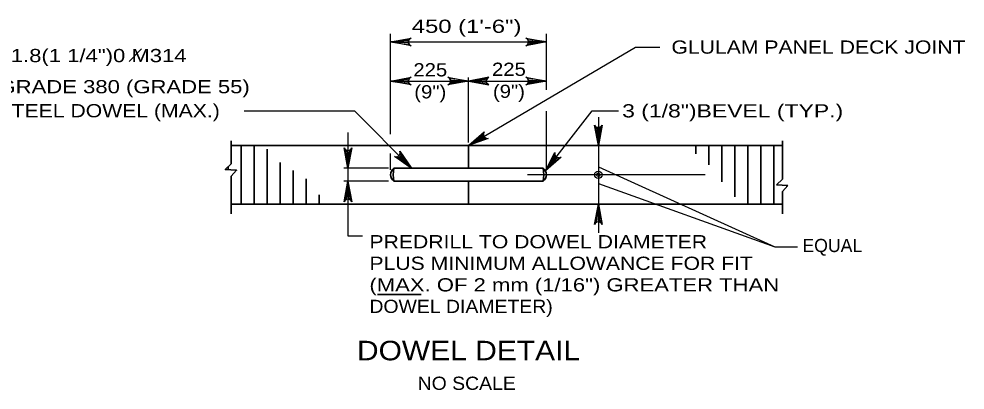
# Model space of a CAD drawing. Extents: x -11 to 79, y -154 to 0.
# Drawn here: x 39.49 to 48.09, y -145.73 to -142.36 of the extents above; entities that cross this region are included whole.
import ezdxf
from ezdxf.enums import TextEntityAlignment as Align

# ---------------------------------------------------------------- set-up
doc = ezdxf.new("R2010")
doc.units = 0
doc.header["$LTSCALE"] = 0.048
for name, color, linetype, lineweight in [('2', 7, 'Continuous', 35), ('3', 7, 'Continuous', 25), ('5', 7, 'Continuous', 25)]:
    doc.layers.add(name, color=color, linetype=linetype, lineweight=lineweight)

msp = doc.modelspace()

# ---------------------------------------------------------------- hatches: boundary and pattern name
at = {"layer": '2'}
msp.add_hatch(color=256, dxfattribs=at).paths.add_polyline_path([(44.27675, -143.73675), (44.28058, -143.73375), (44.27875, -143.73233)])
at = {"layer": '3'}
for points in [[(43.57692, -143.50542), (43.58158, -143.50408), (43.58042, -143.502)], [(42.99258, -143.61842), (42.96583, -143.64508), (43.05925, -143.71208)]]:
    msp.add_hatch(color=256, dxfattribs=at).paths.add_polyline_path(points)

# ---------------------------------------------------------------- linework, layer by layer
at = {"layer": '2'}
for p, q in [((41.41967, -143.4615), (41.41967, -143.67217)), ((41.41967, -143.50542), (46.43392, -143.50542)), ((43.57692, -143.71208), (43.57692, -143.50542)), ((46.43392, -143.4615), (46.43392, -143.80992)), ((41.41967, -143.78458), (41.41967, -144.12508)), ((43.57692, -144.03692), (43.57692, -143.83025)), ((46.43392, -143.80992), (46.37875, -143.862)), ((46.37875, -143.862), (46.48275, -143.86775)), ((41.41967, -144.03692), (46.43392, -144.03692))]:
    msp.add_line(p, q, dxfattribs=at)
at = {"layer": '2', "lineweight": 25}
msp.add_lwpolyline([(44.27675, -143.73675), (44.70158, -143.19142), (44.94242, -143.19142)], dxfattribs=at)
at = {"layer": '2'}
for points in [[(41.41967, -143.67217), (41.3645, -143.72425), (41.4685, -143.73), (41.41967, -143.78458)], [(46.48275, -143.86775), (46.43392, -143.92233), (46.43392, -144.12508)]]:
    msp.add_lwpolyline(points, dxfattribs=at)
at = {"layer": '2', "lineweight": 25}
msp.add_lwpolyline([(44.27675, -143.73675), (44.28058, -143.73375), (44.27875, -143.73233)], close=True, dxfattribs=at)
at = {"layer": '3'}
for p, q in [((42.86825, -143.403), (42.86825, -142.48975)), ((44.28558, -143), (44.28558, -142.48975)), ((42.86825, -142.56433), (44.28558, -142.56433)), ((42.86825, -142.91983), (44.28558, -142.91983)), ((43.57692, -143.4765), (43.57692, -142.8875)), ((41.53575, -143.19042), (42.54, -143.19042)), ((43.05917, -143.71208), (42.54, -143.19042)), ((44.28558, -143.725), (44.28558, -143.19183)), ((44.75808, -143.2465), (44.75808, -144.29992)), ((42.48108, -143.38842), (42.48108, -144.32467)), ((42.86825, -143.725), (42.86825, -143.57733)), ((44.75808, -143.7), (46.36408, -144.42525)), ((42.8485, -143.71208), (42.44408, -143.71208)), ((45.73042, -143.77092), (44.11267, -143.77092)), ((42.8485, -143.83025), (42.44208, -143.83025)), ((42.48108, -144.32467), (42.61242, -144.32467))]:
    msp.add_line(p, q, dxfattribs=at)
at = {"layer": '3', "lineweight": 35}
for p, q in [((40.48967, -142.74083), (40.60225, -142.62817)), ((42.75067, -144.85942), (43.14592, -144.85942))]:
    msp.add_line(p, q, dxfattribs=at)
at = {"layer": '3'}
for points in [[(42.86825, -142.56433), (43.05467, -142.52942), (43.04033, -142.53933), (43.03292, -142.55183), (43.03075, -142.56433), (43.03292, -142.57683), (43.04033, -142.58933), (43.05467, -142.59925), (42.86825, -142.56433), (43.04033, -142.58933), (43.03292, -142.57683), (42.86825, -142.56433), (43.03075, -142.56433), (43.03292, -142.55183), (42.86825, -142.56433), (43.04033, -142.53933)], [(44.28558, -142.56433), (44.09917, -142.59925), (44.1135, -142.58933), (44.12092, -142.57683), (44.12308, -142.56433), (44.12092, -142.55183), (44.1135, -142.53933), (44.09917, -142.52942), (44.28558, -142.56433), (44.1135, -142.53933), (44.12092, -142.55183), (44.28558, -142.56433), (44.12308, -142.56433), (44.12092, -142.57683), (44.28558, -142.56433), (44.1135, -142.58933)], [(43.57692, -143.50542), (45.09617, -142.61083), (45.31717, -142.61083)], [(42.86825, -142.91983), (43.05467, -142.88492), (43.04033, -142.89483), (43.03292, -142.90733), (43.03075, -142.91983), (43.03292, -142.93233), (43.04033, -142.94483), (43.05467, -142.95475), (42.86825, -142.91983), (43.04033, -142.94483), (43.03292, -142.93233), (42.86825, -142.91983), (43.03075, -142.91983), (43.03292, -142.90733), (42.86825, -142.91983), (43.04033, -142.89483)], [(43.57692, -142.91983), (43.3905, -142.95475), (43.40483, -142.94483), (43.41225, -142.93233), (43.41442, -142.91983), (43.41225, -142.90733), (43.40483, -142.89483), (43.3905, -142.88492), (43.57692, -142.91983), (43.40483, -142.89483), (43.41225, -142.90733), (43.57692, -142.91983), (43.41442, -142.91983), (43.41225, -142.93233), (43.57692, -142.91983), (43.40483, -142.94483)], [(43.57692, -142.91983), (43.76333, -142.95475), (43.749, -142.94483), (43.74158, -142.93233), (43.73942, -142.91983), (43.74158, -142.90733), (43.749, -142.89483), (43.76333, -142.88492), (43.57692, -142.91983), (43.749, -142.89483), (43.74158, -142.90733), (43.57692, -142.91983), (43.73942, -142.91983), (43.74158, -142.93233), (43.57692, -142.91983), (43.749, -142.94483)], [(44.28558, -142.91983), (44.09917, -142.95475), (44.1135, -142.94483), (44.12092, -142.93233), (44.12308, -142.91983), (44.12092, -142.90733), (44.1135, -142.89483), (44.09917, -142.88492), (44.28558, -142.91983), (44.1135, -142.89483), (44.12092, -142.90733), (44.28558, -142.91983), (44.12308, -142.91983), (44.12092, -142.93233), (44.28558, -142.91983), (44.1135, -142.94483)], [(44.75808, -143.50542), (44.72317, -143.319), (44.73308, -143.33333), (44.74558, -143.34075), (44.75808, -143.34292), (44.77058, -143.34075), (44.78308, -143.33333), (44.793, -143.319), (44.75808, -143.50542), (44.78308, -143.33333), (44.77058, -143.34075), (44.75808, -143.50542), (44.75808, -143.34292), (44.74558, -143.34075), (44.75808, -143.50542), (44.73308, -143.33333)], [(43.57692, -143.50542), (43.71983, -143.38075), (43.7125, -143.39658), (43.71242, -143.41108), (43.71692, -143.423), (43.72517, -143.43267), (43.73783, -143.43967), (43.75525, -143.44092), (43.57692, -143.50542), (43.73783, -143.43967), (43.72517, -143.43267), (43.57692, -143.50542), (43.71692, -143.423), (43.71242, -143.41108), (43.57692, -143.50542), (43.7125, -143.39658)], [(42.48108, -143.71208), (42.44617, -143.52567), (42.45608, -143.54), (42.46858, -143.54742), (42.48108, -143.54958), (42.49358, -143.54742), (42.50608, -143.54), (42.516, -143.52567), (42.48108, -143.71208), (42.50608, -143.54), (42.49358, -143.54742), (42.48108, -143.71208), (42.48108, -143.54958), (42.46858, -143.54742), (42.48108, -143.71208), (42.45608, -143.54)], [(43.05917, -143.71208), (42.90292, -143.60458), (42.92008, -143.60775), (42.93417, -143.60417), (42.9445, -143.59692), (42.95192, -143.58658), (42.9555, -143.5725), (42.95242, -143.55533), (43.05917, -143.71208), (42.9555, -143.5725), (42.95192, -143.58658), (43.05917, -143.71208), (42.9445, -143.59692), (42.93417, -143.60417), (43.05917, -143.71208), (42.92008, -143.60775)], [(44.27675, -143.73675), (44.36375, -143.56825), (44.36275, -143.58567), (44.36808, -143.59917), (44.37658, -143.60858), (44.38783, -143.61458), (44.40217, -143.61642), (44.41892, -143.61117), (44.27675, -143.73675), (44.40217, -143.61642), (44.38783, -143.61458), (44.27675, -143.73675), (44.37658, -143.60858), (44.36808, -143.59917), (44.27675, -143.73675), (44.36275, -143.58567)], [(42.48108, -143.83025), (42.516, -144.01667), (42.50608, -144.00233), (42.49358, -143.99492), (42.48108, -143.99275), (42.46858, -143.99492), (42.45608, -144.00233), (42.44617, -144.01667), (42.48108, -143.83025), (42.45608, -144.00233), (42.46858, -143.99492), (42.48108, -143.83025), (42.48108, -143.99275), (42.49358, -143.99492), (42.48108, -143.83025), (42.50608, -144.00233)], [(44.75808, -143.85058), (46.36408, -144.42525), (46.56917, -144.42525)], [(44.75808, -144.03692), (44.793, -144.22333), (44.78308, -144.209), (44.77058, -144.20158), (44.75808, -144.19942), (44.74558, -144.20158), (44.73308, -144.209), (44.72317, -144.22333), (44.75808, -144.03692), (44.73308, -144.209), (44.74558, -144.20158), (44.75808, -144.03692), (44.75808, -144.19942), (44.77058, -144.20158), (44.75808, -144.03692), (44.78308, -144.209)]]:
    msp.add_lwpolyline(points, dxfattribs=at)
for points in [[(43.57692, -143.50542), (43.58158, -143.50408), (43.58042, -143.502)], [(42.99258, -143.61842), (42.96583, -143.64508), (43.05925, -143.71208)]]:
    msp.add_lwpolyline(points, close=True, dxfattribs=at)
for radius in [0.03333, 0.01667]:
    msp.add_circle((44.75805, -143.77092), radius, dxfattribs=at)
at = {"layer": '5', "lineweight": 35}
for p, q in [((41.51075, -144.03683), (41.51075, -143.50542)), ((41.62883, -144.03675), (41.62883, -143.50542)), ((45.64458, -143.58042), (45.64458, -143.50542)), ((45.76267, -143.68167), (45.76267, -143.50542)), ((45.88083, -143.835), (45.88083, -143.50542)), ((45.99892, -143.97117), (45.99892, -143.50542)), ((46.117, -144.03458), (46.117, -143.50542)), ((46.23517, -144.03692), (46.23517, -143.50542)), ((46.35325, -144.03692), (46.35325, -143.50542)), ((41.747, -144.03675), (41.747, -143.53958)), ((41.39267, -143.72575), (41.39267, -143.69767)), ((41.86508, -144.03667), (41.86508, -143.6595)), ((41.98317, -144.03658), (41.98317, -143.73117)), ((42.899, -143.71208), (44.25483, -143.71208)), ((42.10125, -144.0365), (42.10125, -143.809)), ((42.898, -143.83025), (44.25583, -143.83025)), ((46.47133, -143.8805), (46.47133, -143.86717)), ((42.21942, -144.03642), (42.21942, -143.95475)), ((42.3375, -144.03633), (42.3375, -144.03175))]:
    msp.add_line(p, q, dxfattribs=at)
for centre, radius, start, end in [((42.94102, -143.77155), 0.07279, 125.25747, 233.72326), ((43.19801, -143.77383), 0.3053, 168.33679, 190.64394), ((43.95579, -143.77383), 0.3053, 349.35606, 11.66321), ((44.21278, -143.77155), 0.07279, 306.27674, 54.74253)]:
    msp.add_arc(centre, radius, start, end, dxfattribs=at)

# ---------------------------------------------------------------- texts
at = {"layer": '3'}
for s, height, width, p in [('450 (1\'-6")', 0.12, 1.35, (43.55996, -142.48175)), ('225', 0.12, 1.15, (43.2295, -142.87733)), ('225', 0.12, 1.15, (43.94467, -142.87258)), ('(9")', 0.12, 1.15, (43.22954, -143.07733)), ('(9")', 0.12, 1.15, (43.94471, -143.07258)), ('DOWEL DETAIL', 0.1772, 1.15, (43.57733, -145.45658)), ('NO SCALE', 0.12, 1.1, (43.56087, -145.72525))]:
    msp.add_text(s, height=height, dxfattribs=dict(at, width=width)).set_placement(p, align=Align.CENTER)
for s, width, p in [('GLULAM PANEL DECK JOINT', 1.2, (45.42275, -142.67083)), ('31.8(1 1/4")0 M314', 1.25, (39.30275, -142.748)), ('GRADE 380 (GRADE 55)', 1.25, (39.30275, -143.03075)), ('STEEL DOWEL (MAX.)', 1.2, (39.29325, -143.24892)), ('3 (1/8")BEVEL (TYP.)', 1.3, (44.9745, -143.25)), ('PREDRILL TO DOWEL DIAMETER', 1.2, (42.67617, -144.43925)), ('PLUS MINIMUM ALLOWANCE FOR FIT', 1.2, (42.67617, -144.63508)), ('(MAX. OF 2 mm (1/16") GREATER THAN', 1.25, (42.67617, -144.83092)), ('DOWEL DIAMETER)', 1.1, (42.67617, -145.02667))]:
    msp.add_text(s, height=0.12, dxfattribs=dict(at, width=width)).set_placement(p)
msp.add_text('EQUAL', height=0.12, dxfattribs=at).set_placement((46.614, -144.4735))

doc.saveas('drawing.dxf')
